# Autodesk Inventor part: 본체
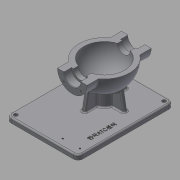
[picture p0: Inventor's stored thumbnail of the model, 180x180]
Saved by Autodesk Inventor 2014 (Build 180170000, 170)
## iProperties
Created: 2015-12
Part Number: 본체
Material: 일반
Document SubType Name: Modeling
Designer: mduedu
Density: 1 g/cm^3
Appearance: 기본값
Mass: 512.305 g
Surface Area: 1121.73 cm^2
Volume: 512.305 cm^3
Author: mduedu
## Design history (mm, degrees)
sketch "스케치1"
  geometry: L1 (-53, 0)-(53, 0); A1 r 53 centre (0, 0) between (53, 0) and (-53, 0); 2 further points
  constraints: 2 coincident, 2 end point, 2 point on circle, 1 centre point, 1 horizontal, 1 midpoint
  dimensions: "d0" = 53 radius of A1
revolve "회전1" sketch "스케치1" stored, may be unused: angle "d2" = 90 deg
feature "쉘1" dims "d11" = 10
node "작업 평면1"
sketch "스케치2"
  geometry: C1 r 31 at (0, 0); 1 further point
  constraints: 1 centre point, 1 coincident
  dimensions: "d4" = 62 diameter of C1
extrude "돌출1" join sketch "스케치2" stored distance "d5" = 10; taper "d6" = 0 deg
hole "구멍1" diameter "d14" = 35; stored, may be unused: countersink angle "d18" = 90 deg, drill point angle "d20" = 0 deg; dims "d12" = 10, "d13" = 10, "d15" = 6, "d16" = 4, "d17" = 2, "d19" = 16
hole "구멍2" diameter "d23" = 27; stored, may be unused: countersink angle "d27" = 90 deg, drill point angle "d29" = 0 deg; dims "d21" = 10, "d22" = 10, "d24" = 6, "d25" = 4, "d26" = 2, "d28" = 16
fillet "모깎기1" dims "d30" = 0.3
chamfer "모따기1" distance "d40" = 1; stored, may be unused: second distance "d41" = 2, angle "d42" = 45 deg
sketch "스케치4"
  geometry: L1 (0, 0)-(0, -25); L2 (0, 0)-(-17.678, -17.678); A1 r 25 centre (0, 0) between (-17.678, -17.678) and (0, -25); 1 further point
  constraints: 4 end point, 2 point on circle, 1 centre point, 1 coincident, 1 vertical
  dimensions: "d43" = 50 diameter of A1; "d47" = 45 deg angle of L1 L2
hole "구멍4" sketch "스케치4" at (-17.678, -17.678) diameter "d49" = 3.242; stored, may be unused: countersink angle "d53" = 90 deg, drill point angle "d55" = 118 deg; dims "d50" = 11, "d51" = 4, "d52" = 2, "d54" = 13
node "작업 평면3"
sketch "스케치6" dims "d22" = 10
  geometry: L1 (-70, -75)-(130, -75); L2 (130, -75)-(130, 75); L3 (130, 75)-(-70, 75); L4 (-70, 75)-(-70, -75); 2 further points
  constraints: 8 end point, 2 parallel, 1 coincident, 1 horizontal, 1 perpendicular
  dimensions: "d158" = 200 distance of L3.end L2.end; "d159" = 150 distance of L2.end L1.end; "d162" = 75 distance from line of L1 point (0, 0); "d163" = 70 distance from line of L4 point (0, 0)
extrude "돌출3" join sketch "스케치6" distance "d80" = 10; taper "d81" = 0 deg
sketch "스케치7"
  geometry: C1 r 20 at (0, 0); 2 further points
  constraints: 2 coincident, 1 centre point
  dimensions: "d82" = 40 diameter of C1
extrude "돌출4" join sketch "스케치7" stored distance "d84" = 10; taper "d85" = 0 deg
sketch "스케치8"
  geometry: 3 further points
  constraints: 2 coincident
hole "구멍6" sketch "스케치8" at (0, 0) diameter "d86" = 20; stored, may be unused: countersink angle "d90" = 90 deg, drill point angle "d92" = 118 deg; dims "d87" = 7, "d88" = 40, "d89" = 5, "d91" = 10
fillet "모깎기2" dims "d93" = 0.3
sketch "스케치9"
  geometry: L1 (-45, -75)-(-38.245, -36.692); L2 (70, -75)-(-130, -75) reference; A1 r 53 centre (0, 0) between (42.988, 31) and (42.988, -31) reference; 1 further point
  constraints: 2 end point, 1 coincident, 1 point on circle, 1 point on line
  dimensions: "d94" = 45 horizontal distance of L1.start point (0, 0); "d160" = 80 deg angle of L2 L1
feature "리브1" sketch "스케치9" dims "d96" = 1, "d97" = 8, "d98" = 0, "d99" = 0, "d100" = 1, "d101" = 1
fillet "모깎기3" dims "d120" = 3
fillet "모깎기4" dims "d121" = 3, "d122" = 3
fillet "모깎기5" dims "d123" = 3
sketch "스케치12"
  geometry: L1 (0, 100)-(0, -100); L2 (0, 100)-(100, 100); L3 (100, 100)-(100, -100); L4 (100, -100)-(0, -100); 2 further points
  constraints: 8 end point, 3 perpendicular, 1 coincident, 1 midpoint, 1 vertical
  dimensions: "d127" = 200 distance of L2.end L3.end; "d129" = 100 distance between parallel lines of L1 L3
extrude "돌출5" cut sketch "스케치12" stored distance "d130" = 10; taper "d131" = 0 deg
fillet "모깎기10" dims "d164" = 10
fillet "모깎기11" dims "d165" = 3
sketch "스케치15"
  geometry: C1 r 4 at (-120, 65); C2 r 4 at (60, 65); C3 r 4 at (60, -65); A1 r 10 centre (-120, 65) between (-120, 75) and (-130, 65) reference; A2 r 10 centre (60, 65) between (70, 65) and (60, 75) reference; A3 r 10 centre (60, -65) between (60, -75) and (70, -65) reference; 1 further point
  constraints: 3 centre point, 3 coincident, 2 equal radius
  dimensions: "d166" = 8 diameter of C1
extrude "돌출8" cut sketch "스케치15" stored distance "d167" = 10; taper "d168" = 0 deg
sketch "스케치16"
  geometry: L1 (-130, 65)-(-130, -65) reference; L2 (-120, -75)-(60, -75) reference; 2 further points
  constraints: 1 other
  dimensions: "d169" = 70 distance from line of point (-60, -55) L1; "d170" = 20 distance from line of point (-60, -55) L2
feature "엠보싱2" sketch "스케치16" dims "d171" = 0.5, "d172" = 0
sketch "스케치17"
  geometry: L1 (-120, 75)-(60, 75) reference; L2 (-130, -65)-(-130, 65) reference; 2 further points
  constraints: 1 vertical alignment
  dimensions: "d180" = 12 distance from line of L1 point (-114, 63); "d181" = 16 distance from line of point (-114, 63) L2; "d182" = 36 distance of point (-114, 27) point (-114, 63)
hole "구멍9" sketch "스케치17" at (-114, 63), (-114, 27) diameter "d173" = 3.242; stored, may be unused: countersink angle "d177" = 90 deg, drill point angle "d179" = 0 deg; dims "d174" = 6, "d175" = 4, "d176" = 2, "d178" = 8
node "솔리드1"
mirror "대칭1"
mirror "대칭2"
pattern_circular "원형 패턴1" dims angle "d57" = 360 deg
mirror "대칭3"
pattern_circular "원형 패턴3" dims angle "d103" = 360 deg
other parameters: "d3" = 67, "d77" = -85
